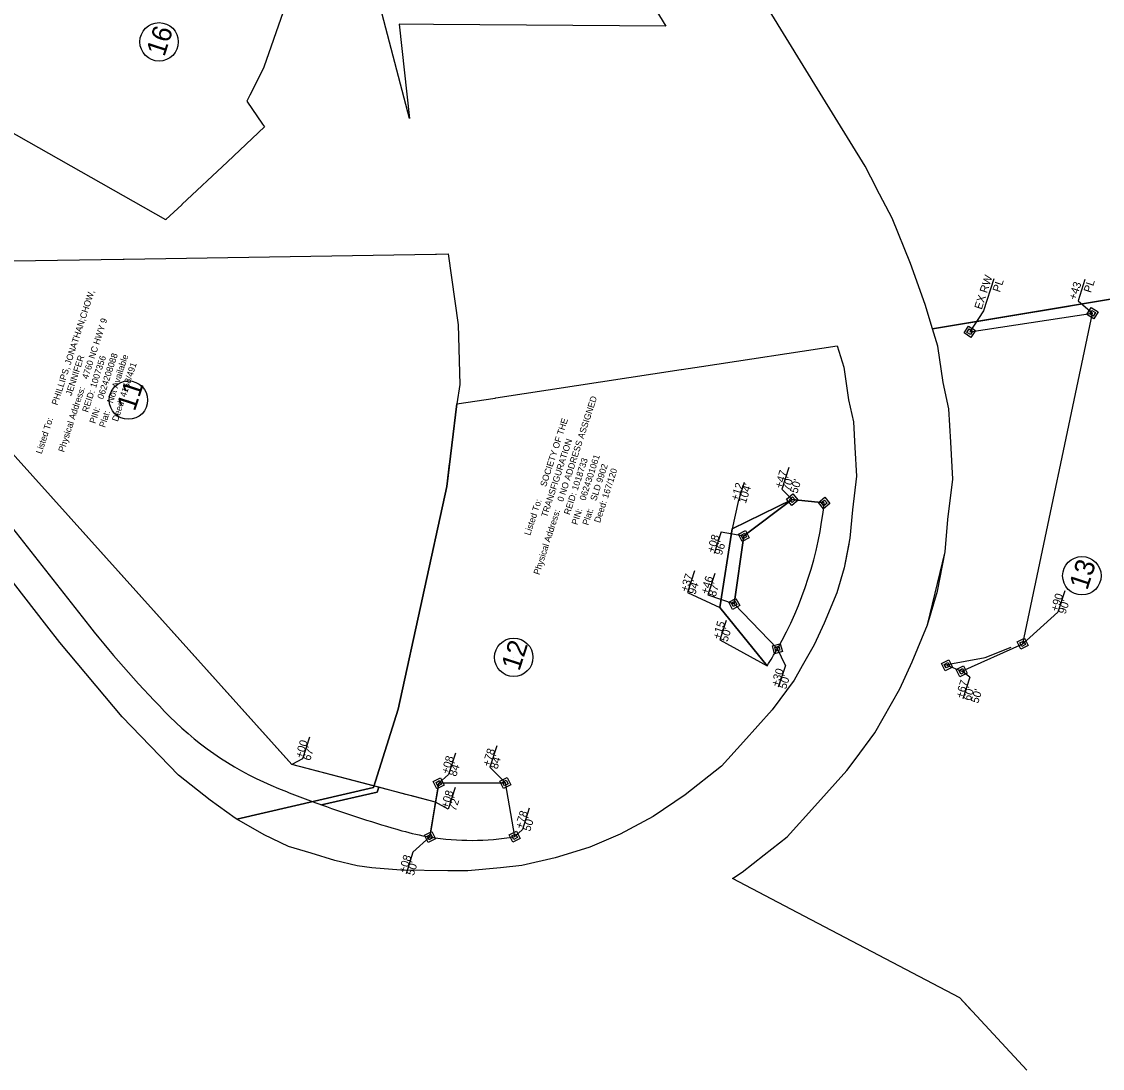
# Model space of a CAD drawing. Extents: x 1019969 to 1024963, y 638146 to 643978.
# Drawn here: x 1022798 to 1023474, y 639731 to 640385 of the extents above; entities that cross this region are included whole.
import ezdxf

# ---------------------------------------------------------------- set-up
doc = ezdxf.new("R2010")
doc.units = 0
for name, color, linetype in [('Old_Level_30', 7, 'Continuous'), ('Pattern 2', 7, 'Continuous'), ('Pattern 5', 7, 'Continuous'), ('Pattern 6', 7, 'Continuous'), ('Prop Easement Construction', 7, 'Continuous'), ('Prop Easement Construction Station Offsets', 7, 'Continuous'), ('Prop Easement Permanent Drainage', 7, 'Continuous'), ('Prop Easement Permanent Drainage Station Offsets', 7, 'Continuous'), ('Prop Easement Temporary Drainage', 7, 'Continuous'), ('Prop Easement Temporary Drainage Station Offsets', 7, 'Continuous'), ('Prop Parcel Number CELL', 7, 'Continuous'), ('Prop Parcel Owner Text', 7, 'Continuous'), ('Prop ROW Marker CELL', 7, 'Continuous'), ('Prop ROW Permanent Easement CELL', 7, 'Continuous'), ('Prop ROW RW Lines', 7, 'Continuous')]:
    doc.layers.add(name, color=color, linetype=linetype)

msp = doc.modelspace()

# ---------------------------------------------------------------- linework, layer by layer
at = {"layer": 'Old_Level_30'}
for points in [[(1022988.86, 640468.59), (1022949.84, 640356.28), (1022949.73, 640356.05), (1022940.94, 640338.75), (1022939.06, 640335.05), (1022948.94, 640320.64), (1022950.08, 640319.01), (1022927.01, 640297.25), (1022898.56, 640270.43), (1022898.48, 640270.34), (1022888.65, 640261.07), (1022888.56, 640260.99), (1022689.3, 640373.74), (1022582.7, 640434.06)], [(1023192.98, 640394.75), (1023200.95, 640381.96), (1023055.72, 640382.98), (1023034.23, 640383.14), (1023040.68, 640324.2), (1023023.75, 640389.4)], [(1023516.15, 640217.54), (1023367.42, 640192.87), (1023362.83, 640208.04), (1023353.72, 640233.66), (1023342.16, 640261.99), (1023332.54, 640280.56), (1023332.5, 640280.65), (1023325.39, 640294.38), (1023297.29, 640340.1), (1023265.41, 640391.98)], [(1022697.66, 640233.85), (1022861.98, 640236.45), (1022862.57, 640236.46), (1023056.92, 640239.52), (1023057.67, 640239.55), (1023065, 640239.69), (1023071.05, 640195.29), (1023072.16, 640157.99), (1023070.3, 640145.97), (1023064.02, 640094.39), (1023033.61, 639955.18), (1023018.3, 639906.29), (1022932.95, 639886.6), (1022931.93, 639887.2), (1022916.34, 639898.41), (1022896.4, 639913.98), (1022861.33, 639950.56), (1022822.41, 639996.85), (1022814.25, 640007.36), (1022786.96, 640042.51)], [(1023426.28, 639729.86), (1023384.49, 639774.86), (1023283.32, 639828.02), (1023242.61, 639849.43), (1023248.48, 639853.44), (1023262.27, 639864.28), (1023276.63, 639875.58), (1023294.01, 639894.77), (1023313.86, 639916.9), (1023319.09, 639923.93), (1023331.46, 639940.55), (1023347, 639968.05), (1023354.8, 639984.85), (1023364.28, 640007.96), (1023375.41, 640053.6), (1023377.12, 640073.72), (1023380.06, 640098.99), (1023378.84, 640122.1), (1023377.62, 640142.82), (1023374.1, 640159.26), (1023370.68, 640182.06), (1023367.42, 640192.87), (1023516.15, 640217.54)], [(1023391, 639767.86), (1023384.49, 639774.86), (1023283.32, 639828.02), (1023242.61, 639849.43), (1023248.48, 639853.44), (1023262.27, 639864.28), (1023276.63, 639875.58), (1023294.01, 639894.77), (1023313.86, 639916.9), (1023319.09, 639923.93), (1023331.46, 639940.55), (1023347, 639968.05), (1023354.8, 639984.85), (1023364.28, 640007.96), (1023370.49, 640029.06), (1023375.41, 640053.6), (1023377.12, 640073.72), (1023380.06, 640098.99), (1023378.84, 640122.1), (1023377.62, 640142.82), (1023374.1, 640159.26), (1023370.68, 640182.06), (1023367.42, 640192.87), (1023452.9, 640207.05)], [(1023315.14, 640058.28), (1023312.18, 640043.46), (1023307.59, 640027.87), (1023299.8, 640008.9), (1023293.58, 639995.49), (1023286.1, 639982.26), (1023281.06, 639973.34), (1023267.36, 639954.92), (1023249.45, 639934.96), (1023235.54, 639919.6), (1023212.96, 639901.83), (1023193.02, 639888.21), (1023172.43, 639877.2), (1023153.46, 639869.14), (1023139.3, 639864.73), (1023131.75, 639862.37), (1023110.85, 639857.64), (1023097.64, 639856.22), (1023077.1, 639854.22), (1023064.79, 639854.22), (1023035.31, 639854.73), (1023017.15, 639856.2), (1023008.03, 639857.5), (1022994.17, 639860.74), (1022979.41, 639865.32), (1022965.22, 639869.57), (1022950.04, 639876.72), (1022932.95, 639886.6), (1023018.3, 639906.29), (1023033.61, 639955.18), (1023064.02, 640094.39), (1023065.76, 640108.7)], [(1023375.38, 639982.91), (1023400.25, 639987.48), (1023416.51, 639993.94)]]:
    msp.add_lwpolyline(points, dxfattribs=at)
msp.add_lwpolyline([(1023077.1, 639854.22), (1023064.79, 639854.22), (1023035.31, 639854.73), (1023017.15, 639856.2), (1023008.03, 639857.5), (1022994.17, 639860.74), (1022979.41, 639865.32), (1022965.22, 639869.57), (1022950.04, 639876.72), (1022932.95, 639886.6), (1023018.3, 639906.29), (1023033.61, 639955.18), (1023064.02, 640094.39), (1023070.3, 640145.97), (1023094.25, 640149.63), (1023094.68, 640149.69), (1023094.76, 640149.7), (1023210.44, 640167.35), (1023210.56, 640167.38), (1023223.1, 640169.28), (1023223.18, 640169.29), (1023307.95, 640182.23), (1023311.99, 640168.88), (1023315.04, 640148.51), (1023318, 640134.74), (1023318.93, 640118.77), (1023319.88, 640100.89), (1023317.42, 640079.74), (1023315.91, 640062.08), (1023312.18, 640043.46), (1023307.59, 640027.87), (1023299.8, 640008.9), (1023293.58, 639995.49), (1023286.1, 639982.26), (1023281.06, 639973.34), (1023267.36, 639954.92), (1023249.45, 639934.96), (1023235.54, 639919.6), (1023212.96, 639901.83), (1023193.02, 639888.21), (1023172.43, 639877.2), (1023153.46, 639869.14), (1023139.3, 639864.73), (1023131.75, 639862.37), (1023110.85, 639857.64), (1023097.64, 639856.22)], close=True, dxfattribs=at)
at = {"layer": 'Pattern 2'}
for p, q in [((1023279.88, 640086.16), (1023242.41, 640067.85)), ((1023279.88, 640086.16), (1023249.59, 640063.48)), ((1023249.59, 640063.48), (1023279.88, 640086.16)), ((1023299.77, 640084.08), (1023279.88, 640086.16)), ((1023242.41, 640067.85), (1023234.55, 640018.82)), ((1023249.59, 640063.48), (1023243.58, 640021.06)), ((1023243.58, 640021.06), (1023249.59, 640063.48)), ((1023234.55, 640018.82), (1023264.16, 639982.41)), ((1023243.58, 640021.06), (1023270.54, 639992.98)), ((1023270.54, 639992.98), (1023243.58, 640021.06)), ((1023100.64, 639909.16), (1023059.04, 639908.98)), ((1023106.46, 639875.66), (1023100.64, 639909.16))]:
    msp.add_line(p, q, dxfattribs=at)
msp.add_lwpolyline([(1023059.04, 639908.98), (1023057.08, 639897.14), (1023053.5, 639875.43)], dxfattribs=at)
for centre, radius, start, end in [((1023067.64, 640108.32), 233.39, 330.38486, 354.03984), ((1023067.64, 640108.32), 233.39, 327.35217, 330.38486), ((1023079.31, 640031.9), 158.58, 260.63289, 279.85852)]:
    msp.add_arc(centre, radius, start, end, dxfattribs=at)
at = {"layer": 'Pattern 6'}
for p, q in [((1022965.65, 639922.52), (1022762.71, 640148.33)), ((1022783.3, 640080.08), (1022840.86, 640007.16)), ((1022967.3, 639920.68), (1022965.65, 639922.52)), ((1023021.58, 639906.45), (1022967.3, 639920.68)), ((1023021.58, 639906.45), (1023020.59, 639903.32)), ((1023020.59, 639903.32), (1023021.58, 639906.45)), ((1023038.49, 639902.02), (1023021.58, 639906.45)), ((1023020.59, 639903.32), (1022985.71, 639895.52)), ((1022985.71, 639895.52), (1023020.59, 639903.32)), ((1023042.17, 639901.05), (1023038.49, 639902.02)), ((1023057.08, 639897.14), (1023042.17, 639901.05)), ((1023055.88, 639889.89), (1023057.08, 639897.14)), ((1023053.5, 639875.43), (1023055.57, 639888.01)), ((1023055.57, 639888.01), (1023055.88, 639889.89))]:
    msp.add_line(p, q, dxfattribs=at)
for centre, radius, start, end in [((1023352.43, 640410.95), 651.73, 218.28466, 224.94478), ((1023034.49, 640093.62), 202.53, 224.94478, 248.08344), ((1023246.66, 640620.98), 770.97, 248.08344, 250.21613), ((1023246.66, 640620.98), 770.97, 250.21613, 254.14272), ((1023079.31, 640031.81), 158.49, 254.14272, 260.6273)]:
    msp.add_arc(centre, radius, start, end, dxfattribs=at)
at = {"layer": 'Prop Easement Construction'}
for p, q in [((1022967.3, 639920.68), (1022762.71, 640148.33)), ((1023057.08, 639897.14), (1022967.3, 639920.68))]:
    msp.add_line(p, q, dxfattribs=at)
at = {"layer": 'Prop Easement Construction Station Offsets'}
for p, q in [((1022978.27, 639937.74), (1022973.89, 639924.27)), ((1023069.2, 639906.24), (1023064.85, 639892.85))]:
    msp.add_line(p, q, dxfattribs=at)
for points in [[(1022973.89, 639924.27), (1022967.3, 639920.68)], [(1023064.85, 639892.85), (1023057.08, 639897.14)]]:
    msp.add_lwpolyline(points, dxfattribs=at)
at = {"layer": 'Prop Easement Permanent Drainage'}
for p, q in [((1023390.73, 640191.01), (1023467.4, 640202.62)), ((1023423.78, 639996.14), (1023467.4, 640202.62)), ((1023249.59, 640063.48), (1023279.88, 640086.16)), ((1023279.88, 640086.16), (1023299.77, 640084.08)), ((1023243.58, 640021.06), (1023249.59, 640063.48)), ((1023270.54, 639992.98), (1023243.58, 640021.06)), ((1023385.72, 639978.94), (1023423.78, 639996.14)), ((1023376.46, 639982.7), (1023385.72, 639978.94)), ((1023053.5, 639875.43), (1023059.04, 639908.98)), ((1023059.04, 639908.98), (1023100.64, 639909.16)), ((1023106.46, 639875.66), (1023100.64, 639909.16))]:
    msp.add_line(p, q, dxfattribs=at)
at = {"layer": 'Prop Easement Permanent Drainage Station Offsets'}
for p, q in [((1023405.79, 640224), (1023399.32, 640204.12)), ((1023462.66, 640223.68), (1023458.33, 640210.33)), ((1023277.76, 640106.27), (1023273.37, 640092.76)), ((1023235.36, 640065.99), (1023231.01, 640052.6)), ((1023231.47, 640040.06), (1023227.13, 640026.69)), ((1023450.09, 640029.29), (1023445.71, 640015.83)), ((1023275.52, 639982.46), (1023271.14, 639968.99)), ((1023390.73, 639975.16), (1023386.33, 639961.66)), ((1023095.22, 639932.4), (1023090.86, 639919.01)), ((1023069.45, 639927.76), (1023065.1, 639914.37)), ((1023115.6, 639893.53), (1023111.25, 639880.14)), ((1023042.93, 639865.87), (1023038.58, 639852.48))]:
    msp.add_line(p, q, dxfattribs=at)
for points in [[(1023458.33, 640210.33), (1023467.4, 640202.62)], [(1023399.32, 640204.12), (1023390.73, 640191.01)], [(1023273.37, 640092.76), (1023279.88, 640086.16)], [(1023235.36, 640065.99), (1023249.59, 640063.48)], [(1023227.13, 640026.69), (1023243.58, 640021.06)], [(1023445.71, 640015.83), (1023423.78, 639996.14)], [(1023275.52, 639982.46), (1023270.54, 639992.98)], [(1023390.73, 639975.16), (1023385.72, 639978.94)], [(1023090.86, 639919.01), (1023100.64, 639909.16)], [(1023065.1, 639914.37), (1023059.04, 639908.98)], [(1023111.25, 639880.14), (1023106.46, 639875.66)], [(1023042.93, 639865.87), (1023053.5, 639875.43)]]:
    msp.add_lwpolyline(points, dxfattribs=at)
at = {"layer": 'Prop Easement Temporary Drainage'}
for p, q in [((1023242.41, 640067.85), (1023279.88, 640086.16)), ((1023234.55, 640018.82), (1023242.41, 640067.85)), ((1023264.16, 639982.41), (1023234.55, 640018.82))]:
    msp.add_line(p, q, dxfattribs=at)
at = {"layer": 'Prop Easement Temporary Drainage Station Offsets'}
for p, q in [((1023249.87, 640096.93), (1023245.99, 640084.97)), ((1023218.85, 640041.63), (1023214.46, 640028.12)), ((1023238.5, 640010.71), (1023234.54, 639998.53))]:
    msp.add_line(p, q, dxfattribs=at)
for points in [[(1023245.99, 640084.97), (1023242.41, 640067.85)], [(1023214.46, 640028.12), (1023234.55, 640018.82)], [(1023234.54, 639998.53), (1023264.16, 639982.41)]]:
    msp.add_lwpolyline(points, dxfattribs=at)
at = {"layer": 'Prop Parcel Number CELL'}
for p, q in [((1022884.34, 640372.12), (1022884.34, 640372.12)), ((1022865.18, 640148.33), (1022865.18, 640148.33)), ((1023460.75, 640038.6), (1023460.75, 640038.6)), ((1023105.87, 639987.67), (1023105.87, 639987.67))]:
    msp.add_line(p, q, dxfattribs=at)
for centre in [(1022884.34, 640372.12), (1022865.18, 640148.33), (1023460.75, 640038.6), (1023105.87, 639987.67)]:
    msp.add_circle(centre, 12, dxfattribs=at)
at = {"layer": 'Prop ROW Marker CELL'}
for p, q in [((1023467.4, 640202.62), (1023467.4, 640202.62)), ((1023390.73, 640191.01), (1023390.73, 640191.01)), ((1023279.88, 640086.16), (1023279.88, 640086.16)), ((1023299.77, 640084.08), (1023299.77, 640084.08)), ((1023249.59, 640063.48), (1023249.59, 640063.48)), ((1023243.58, 640021.06), (1023243.58, 640021.06)), ((1023270.54, 639992.98), (1023270.54, 639992.98)), ((1023423.78, 639996.14), (1023423.78, 639996.14)), ((1023376.46, 639982.7), (1023376.46, 639982.7)), ((1023385.72, 639978.94), (1023385.72, 639978.94)), ((1023059.04, 639908.98), (1023059.04, 639908.98)), ((1023100.64, 639909.16), (1023100.64, 639909.16)), ((1023053.5, 639875.43), (1023053.5, 639875.43)), ((1023106.46, 639875.66), (1023106.46, 639875.66))]:
    msp.add_line(p, q, dxfattribs=at)
at = {"layer": 'Prop ROW Permanent Easement CELL'}
for points in [[(1023466.65, 640206.14), (1023470.92, 640203.37), (1023468.14, 640199.1), (1023463.87, 640201.87)], [(1023467.02, 640204.38), (1023469.16, 640202.99), (1023467.77, 640200.86), (1023465.63, 640202.25)], [(1023389.99, 640194.54), (1023394.26, 640191.76), (1023391.48, 640187.49), (1023387.21, 640190.27)], [(1023390.36, 640192.78), (1023392.5, 640191.39), (1023391.11, 640189.25), (1023388.97, 640190.64)], [(1023276.29, 640086.49), (1023280.21, 640089.75), (1023283.46, 640085.83), (1023279.55, 640082.58)], [(1023278.09, 640086.33), (1023280.05, 640087.95), (1023281.67, 640085.99), (1023279.71, 640084.37)], [(1023296.19, 640084.46), (1023300.14, 640087.66), (1023303.35, 640083.71), (1023299.4, 640080.5)], [(1023297.98, 640084.27), (1023299.96, 640085.87), (1023301.56, 640083.9), (1023299.58, 640082.29)], [(1023246.16, 640064.59), (1023250.7, 640066.9), (1023253.01, 640062.36), (1023248.48, 640060.05)], [(1023247.88, 640064.03), (1023250.14, 640065.19), (1023251.3, 640062.92), (1023249.03, 640061.76)], [(1023240.16, 640022.17), (1023244.69, 640024.48), (1023247, 640019.94), (1023242.47, 640017.63)], [(1023241.87, 640021.61), (1023244.14, 640022.77), (1023245.29, 640020.5), (1023243.02, 640019.35)], [(1023420.36, 639997.25), (1023424.89, 639999.56), (1023427.2, 639995.02), (1023422.67, 639992.71)], [(1023267.42, 639994.78), (1023272.34, 639996.1), (1023273.66, 639991.19), (1023268.75, 639989.86)], [(1023268.98, 639993.88), (1023271.44, 639994.54), (1023272.1, 639992.09), (1023269.65, 639991.42)], [(1023422.07, 639996.69), (1023424.34, 639997.85), (1023425.49, 639995.58), (1023423.22, 639994.42)], [(1023373.04, 639983.82), (1023377.58, 639986.13), (1023379.88, 639981.59), (1023375.35, 639979.28)], [(1023374.75, 639983.26), (1023377.02, 639984.41), (1023378.17, 639982.15), (1023375.91, 639980.99)], [(1023382.3, 639980.05), (1023386.84, 639982.36), (1023389.15, 639977.82), (1023384.61, 639975.51)], [(1023384.01, 639979.49), (1023386.28, 639980.65), (1023387.44, 639978.38), (1023385.17, 639977.22)], [(1023055.61, 639910.09), (1023060.15, 639912.4), (1023062.46, 639907.87), (1023057.92, 639905.56)], [(1023057.32, 639909.54), (1023059.59, 639910.69), (1023060.75, 639908.42), (1023058.48, 639907.27)], [(1023097.21, 639910.27), (1023101.75, 639912.58), (1023104.06, 639908.05), (1023099.52, 639905.74)], [(1023098.93, 639909.72), (1023101.19, 639910.87), (1023102.35, 639908.6), (1023100.08, 639907.45)], [(1023050.08, 639876.55), (1023054.61, 639878.86), (1023056.92, 639874.32), (1023052.39, 639872.01)], [(1023051.79, 639875.99), (1023054.06, 639877.15), (1023055.21, 639874.88), (1023052.94, 639873.72)], [(1023103.04, 639876.77), (1023107.58, 639879.09), (1023109.88, 639874.55), (1023105.35, 639872.24)], [(1023104.75, 639876.22), (1023107.02, 639877.37), (1023108.17, 639875.11), (1023105.91, 639873.95)]]:
    msp.add_lwpolyline(points, close=True, dxfattribs=at)
at = {"layer": 'Prop ROW RW Lines'}
msp.add_arc((1022167.9, 640774.19), 948.09, 40.00236, 40.00236, dxfattribs=at)

# ---------------------------------------------------------------- texts
at = {"layer": 'Pattern 5'}
for s, p in [('PHILLIPS, JONATHAN;CHOW, ', (1022820.88, 640144.85)), ('4760 NC HWY 9', (1022839.84, 640161.13)), ('JENNIFER', (1022829.63, 640150.76)), ('1007356', (1022844.87, 640155.56)), ('0624208088', (1022849.43, 640148.58)), ('Not Available', (1022855.46, 640146.11)), ('4158/491', (1022863.52, 640149.86)), ('Physical Address:', (1022825, 640115.48)), ('REID:', (1022839.92, 640140.35)), ('Deed:', (1022858.57, 640134.64)), ('0 NO ADDRESS ASSIGNED', (1023136.68, 640084.54)), ('PIN:', (1022844.48, 640133.36)), ('Plat:', (1022850.52, 640130.9)), ('Listed To:', (1022810.98, 640114.42)), ('SOCIETY OF THE ', (1023126.04, 640093.89)), ('TRANSFIGURATION', (1023126.68, 640074.8)), ('0624301061', (1023150.58, 640085.27)), ('1018733', (1023145.8, 640091.58)), ('SLD 9902', (1023157.35, 640085.07)), ('167/120', (1023164.67, 640086.56)), ('Listed To:', (1023116.15, 640063.45)), ('REID:', (1023140.85, 640076.36)), ('Physical Address:', (1023121.83, 640038.89)), ('PIN:', (1023145.64, 640070.05)), ('Plat:', (1023152.41, 640069.85)), ('Deed:', (1023159.72, 640071.34))]:
    msp.add_text(s, height=4, rotation=71.9892, dxfattribs=at).set_placement(p)
at = {"layer": 'Prop Easement Construction Station Offsets'}
for s, p in [('+00', (1022973.87, 639924.28)), ("67'", (1022978.67, 639922.72)), ('+08', (1023064.83, 639892.86)), ("72'", (1023069.63, 639891.3))]:
    msp.add_text(s, height=5, rotation=71.99034, dxfattribs=at).set_placement(p)
at = {"layer": 'Prop Easement Permanent Drainage Station Offsets'}
for s, p in [('EX RW', (1023398.16, 640204.58)), ('PL', (1023409.54, 640215.34)), ('+43', (1023457.06, 640210.48)), ('PL', (1023466.42, 640215.02)), ('+47', (1023273.35, 640092.77)), ("70'", (1023278.15, 640091.21)), ("50'", (1023282.95, 640089.65)), ('+08', (1023230.99, 640052.61)), ("96'", (1023235.79, 640051.05)), ('+46', (1023227.1, 640026.7)), ("87'", (1023231.9, 640025.14)), ('+90', (1023445.69, 640015.84)), ("90'", (1023450.49, 640014.27)), ('+30', (1023271.12, 639969)), ("50'", (1023275.92, 639967.44)), ('+67', (1023386.31, 639961.66)), ("60'", (1023391.11, 639960.1)), ("50'", (1023395.92, 639958.54)), ('+78', (1023090.84, 639919.02)), ('+08', (1023065.08, 639914.38)), ("84'", (1023095.64, 639917.45)), ("84'", (1023069.88, 639912.82)), ('+78', (1023111.23, 639880.14)), ("50'", (1023116.03, 639878.58)), ('+08', (1023038.56, 639852.49)), ("50'", (1023043.36, 639850.93))]:
    msp.add_text(s, height=5, rotation=71.99034, dxfattribs=at).set_placement(p)
at = {"layer": 'Prop Easement Temporary Drainage Station Offsets'}
for s, p in [('+12', (1023245.96, 640084.98)), ("104'", (1023250.76, 640083.42)), ('+37', (1023214.44, 640028.13)), ("94'", (1023219.24, 640026.56)), ('+15', (1023234.52, 639998.54)), ("50'", (1023239.32, 639996.98))]:
    msp.add_text(s, height=5, rotation=71.99034, dxfattribs=at).set_placement(p)
at = {"layer": 'Prop Parcel Owner Text'}
for s, p in [('16', (1022887.58, 640362.43)), ('11', (1022869.17, 640140.94)), ('13', (1023464.06, 640029.14)), ('12', (1023109.32, 639978.63))]:
    msp.add_text(s, height=12.15, rotation=71.9892, dxfattribs=at).set_placement(p)

doc.saveas('drawing.dxf')
